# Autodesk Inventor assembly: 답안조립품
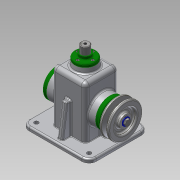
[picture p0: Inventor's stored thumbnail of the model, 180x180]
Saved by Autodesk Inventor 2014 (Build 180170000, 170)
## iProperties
Created: 2016-08
Part Number: 답안조립품
Document SubType Name: Assembly
Designer: user
Author: user
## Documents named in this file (19)
- C:\Users\user\Desktop\460820V1004\답안조립품.iam
- C:\Users\user\Desktop\460820V1004\본체.ipt
- C:\Users\user\Desktop\460820V1004\앞커버.ipt
- C:\Users\user\Desktop\460820V1004\뒤커버.ipt
- C:\Users\user\Desktop\460820V1004\베어링 15 x 35 x 11.ipt
- C:\Users\user\Desktop\460820V1004\편심축.ipt
- C:\Users\user\Desktop\460820V1004\멈춤링 15 x 1.ipt
- C:\Users\user\Desktop\460820V1004\오일실 15 25 7.ipt
- C:\Users\user\Desktop\460820V1004\링크.ipt
- C:\Users\user\Desktop\460820V1004\슬라이드바.ipt
- C:\Users\user\Desktop\460820V1004\고정핀.ipt
- C:\Users\user\Desktop\460820V1004\멈춤링 6 x 5.ipt
- C:\Users\user\Desktop\460820V1004\상부부시.ipt
- C:\Users\user\Desktop\460820V1004\키 5 x 5 x 14.ipt
- C:\Users\user\Desktop\460820V1004\V-벨트풀리.ipt
- C:\Users\user\Desktop\460820V1004\볼트 M6 x 12.ipt
- C:\Users\user\Desktop\460820V1004\와셔.ipt
- C:\Users\user\Desktop\460820V1004\볼트 M3 x 8.ipt
- C:\Users\user\Desktop\460820V1004\볼트 M4 x 10.ipt
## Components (15 placed, 5 different names)
1. 고정핀:1 — 강체:1
2. V-벨트풀리:1 — 각도:1
3. ISO 4018 M6 x 12:1 — 강체:2
4. ISO 4762 M3 x 8:1 — 강체:3
5. ISO 4762 M3 x 8:2
6. ISO 4762 M3 x 8:3
7. ISO 4762 M3 x 8:4
8. ISO 4762 M4 x 10:1 — 강체:4
9. ISO 4762 M4 x 10:3
10. ISO 4762 M4 x 10:4
11. ISO 4762 M4 x 10:5
12. ISO 4762 M4 x 10:2 — 강체:5
13. ISO 4762 M4 x 10:6
14. ISO 4762 M4 x 10:7
15. ISO 4762 M4 x 10:8
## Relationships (6: WeldJoint 5, Angle 1)
- 강체:1 [WeldJoint]: 고정핀:1
- 각도:1 [Angle]: V-벨트풀리:1
- 강체:2 [WeldJoint]: ISO 4018 M6 x 12:1
- 강체:3 [WeldJoint]: ISO 4762 M3 x 8:1
- 강체:4 [WeldJoint]: ISO 4762 M4 x 10:1
- 강체:5 [WeldJoint]: ISO 4762 M4 x 10:2
